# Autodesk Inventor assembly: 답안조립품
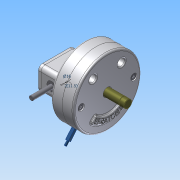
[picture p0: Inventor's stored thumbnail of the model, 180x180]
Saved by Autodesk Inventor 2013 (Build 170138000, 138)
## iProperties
Created: 2015-04
Part Number: 답안조립품
Document SubType Name: Assembly
Designer: Administrator
Mass: 3993.57 g
Surface Area: 3333.7 cm^2
Volume: 1144.49 cm^3
Density: 3.4894 g/cm^3
Author: Administrator
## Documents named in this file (15)
- C:\Users\Administrator\Desktop\350406V1046\답안조립품.iam
- C:\Users\Administrator\Desktop\350406V1046\본체.ipt
- C:\Users\Administrator\Desktop\350406V1046\커버.ipt
- C:\Users\Administrator\Desktop\350406V1046\축.ipt
- C:\Users\Administrator\Desktop\350406V1046\슬라이더.ipt
- C:\Users\Administrator\Desktop\350406V1046\슬라이더2.ipt
- C:\Users\Administrator\Desktop\350406V1046\슬라이더3.ipt
- C:\Users\Administrator\Desktop\350406V1046\커버2.ipt
- C:\Users\Administrator\Desktop\350406V1046\스프링-[가변].ipt
- C:\Users\Administrator\Desktop\350406V1046\멈춤링.ipt
- C:\Users\Administrator\Desktop\350406V1046\베어링62_22.ipt
- C:\Users\Administrator\Desktop\350406V1046\부시.ipt
- C:\Users\Administrator\Desktop\350406V1046\평행핀.ipt
- C:\Users\Administrator\Desktop\350406V1046\M 10 x 35.ipt
- C:\Users\Administrator\Desktop\350406V1046\M 5 x 12.ipt
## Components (5 placed, 3 different names)
1. KS B 1320 B B 5 x  20:1 — 플러쉬:1
2. M 10 x 35:1
3. M 10 x 35:2
4. M 5 x 12:1
5. M 5 x 12:2
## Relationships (1: Flush 1)
- 플러쉬:1 [Flush]: KS B 1320 B B 5 x  20:1
